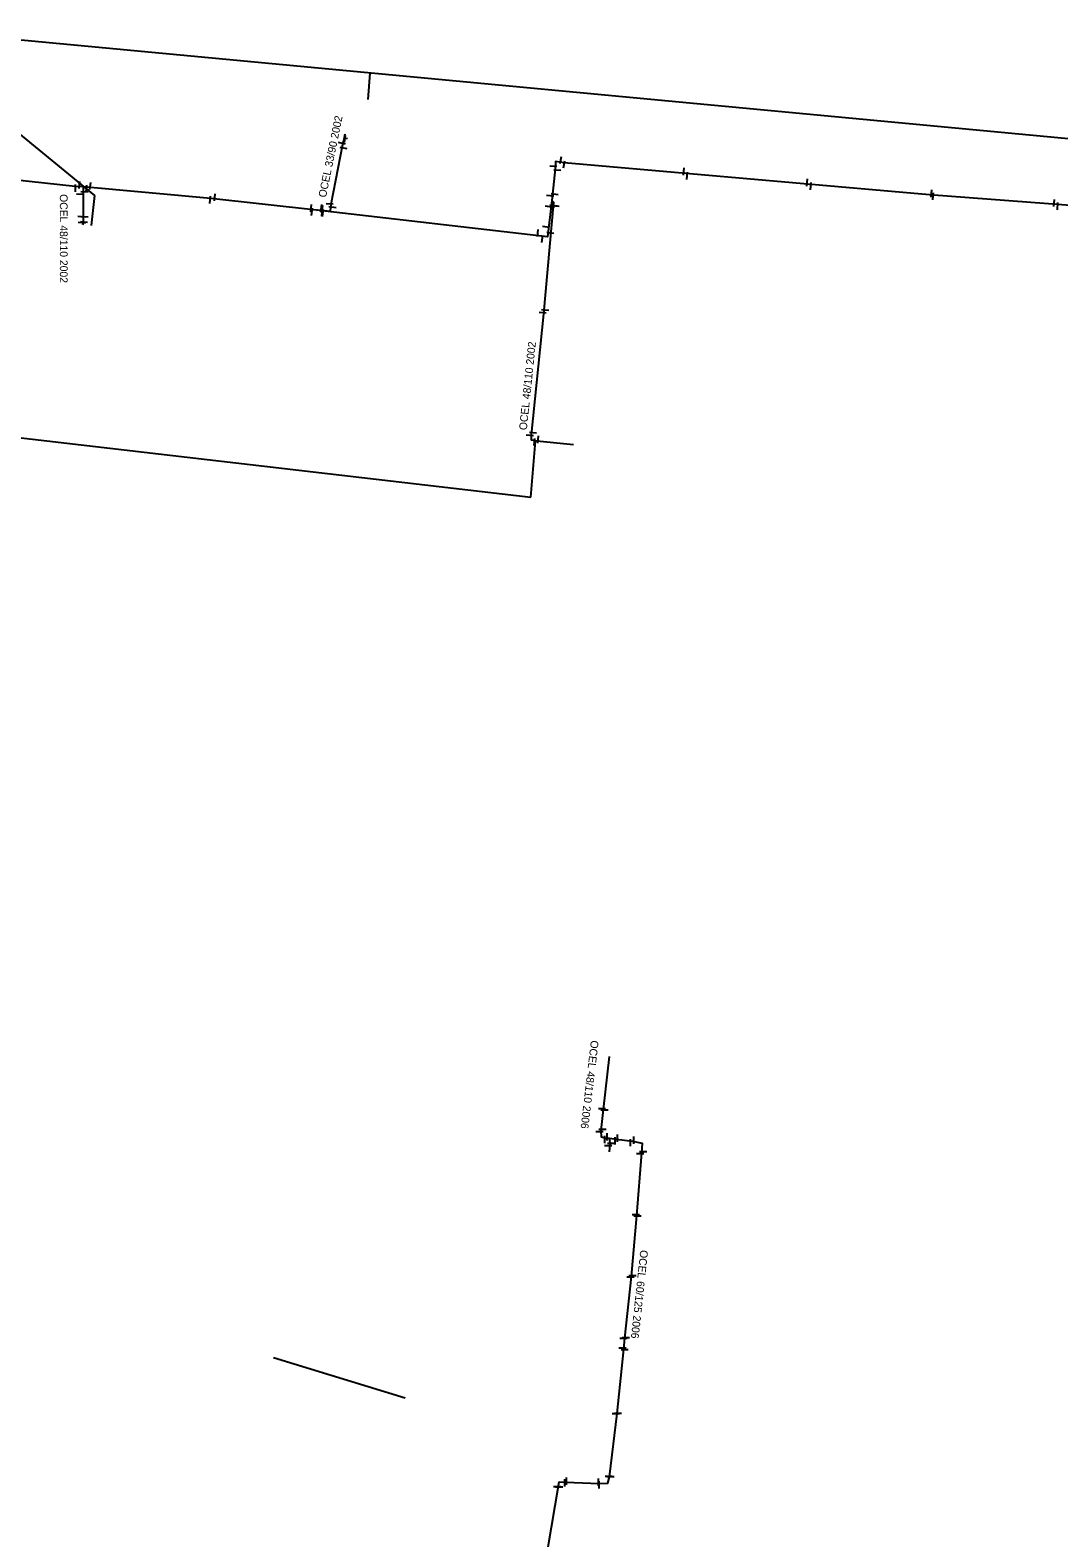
# Model space of a CAD drawing. Extents: x -642943 to -623314, y -1138561 to -1113539.
# Drawn here: x -642652 to -642552.6, y -1114240.7 to -1114094.9 of the extents above; entities that cross this region are included whole.
import ezdxf

# ---------------------------------------------------------------- set-up
doc = ezdxf.new("R2010")
doc.units = 0
for name, color, linetype in [('horkovod dimenze', 7, 'Continuous'), ('horkovod předisol', 7, 'Continuous'), ('horkovod sváry', 7, 'Continuous'), ('horkovod trasa', 7, 'Continuous'), ('horkovod zrušený', 7, 'Continuous')]:
    doc.layers.add(name, color=color, linetype=linetype)

# ---------------------------------------------------------------- blocks, each defined once
blk = doc.blocks.new('SPH')
at = {"layer": 'horkovod sváry'}
blk.add_line((0, -0.035), (0, 0.035), dxfattribs=at)

msp = doc.modelspace()

# ---------------------------------------------------------------- linework, layer by layer
at = {"layer": 'horkovod předisol'}
for points in [[(-642646.93, -1114110.09), (-642647.68, -1114110.06), (-642659.59, -1114108.78), (-642670.77, -1114107.73), (-642683.7, -1114106.45)], [(-642624.37, -1114112.36), (-642624.25, -1114112.32), (-642623.03, -1114112.45), (-642622.95, -1114111.77), (-642621.81, -1114105.98), (-642621.67, -1114105.41), (-642621.38, -1114105.39)], [(-642540.43, -1114112.75), (-642565.12, -1114110.86), (-642600.43, -1114107.77), (-642601.27, -1114107.64), (-642601.29, -1114108.35), (-642601.64, -1114111.42)], [(-642646.93, -1114110.09), (-642646.93, -1114113.56), (-642646.98, -1114113.75)], [(-642624.37, -1114112.36), (-642634.58, -1114111.22), (-642646.93, -1114110.09)], [(-642601.64, -1114111.42), (-642602.04, -1114114.92), (-642624.37, -1114112.36)], [(-642601.64, -1114111.42), (-642601.48, -1114111.57), (-642602.42, -1114122.38), (-642603.61, -1114134.06), (-642603.62, -1114134.54), (-642603.07, -1114134.64), (-642599.52, -1114134.99)], [(-642596.05, -1114202.09), (-642596.4, -1114202.06), (-642596.84, -1114201.95), (-642596.86, -1114201.31), (-642596.64, -1114199.27), (-642596.04, -1114194.14)], [(-642602.05, -1114241.92), (-642600.93, -1114235.27), (-642600.27, -1114235.29), (-642597.05, -1114235.43), (-642596.21, -1114235.39), (-642596.06, -1114234.78), (-642595.32, -1114228.66), (-642594.68, -1114222.43), (-642594.57, -1114221.38), (-642593.92, -1114215.42), (-642593.41, -1114209.53), (-642592.92, -1114203.45), (-642592.85, -1114202.55), (-642593.81, -1114202.35), (-642595.4, -1114202.17), (-642596.05, -1114202.09)], [(-642596.05, -1114202.09), (-642596.02, -1114202.69), (-642596.08, -1114203.35)]]:
    msp.add_lwpolyline(points, dxfattribs=at)
at = {"layer": 'horkovod trasa'}
for points in [[(-642646.93, -1114110.09), (-642647.68, -1114110.06), (-642659.59, -1114108.78), (-642670.77, -1114107.73), (-642683.7, -1114106.45)], [(-642624.37, -1114112.36), (-642624.25, -1114112.32), (-642623.03, -1114112.45), (-642622.95, -1114111.77), (-642621.81, -1114105.98), (-642621.67, -1114105.41), (-642621.38, -1114105.39)], [(-642540.43, -1114112.75), (-642565.12, -1114110.86), (-642600.43, -1114107.77), (-642601.27, -1114107.64), (-642601.29, -1114108.35), (-642601.64, -1114111.42)], [(-642646.93, -1114110.09), (-642646.93, -1114113.56), (-642646.98, -1114113.75)], [(-642624.37, -1114112.36), (-642634.58, -1114111.22), (-642646.93, -1114110.09)], [(-642601.64, -1114111.42), (-642602.04, -1114114.92), (-642624.37, -1114112.36)], [(-642601.64, -1114111.42), (-642601.48, -1114111.57), (-642602.42, -1114122.38), (-642603.61, -1114134.06), (-642603.62, -1114134.54), (-642603.07, -1114134.64), (-642599.52, -1114134.99)], [(-642596.05, -1114202.09), (-642596.4, -1114202.06), (-642596.84, -1114201.95), (-642596.86, -1114201.31), (-642596.64, -1114199.27), (-642596.04, -1114194.14)], [(-642602.05, -1114241.92), (-642600.93, -1114235.27), (-642600.27, -1114235.29), (-642597.05, -1114235.43), (-642596.21, -1114235.39), (-642596.06, -1114234.78), (-642595.32, -1114228.66), (-642594.68, -1114222.43), (-642594.57, -1114221.38), (-642593.92, -1114215.42), (-642593.41, -1114209.53), (-642592.92, -1114203.45), (-642592.85, -1114202.55), (-642593.81, -1114202.35), (-642595.4, -1114202.17), (-642596.05, -1114202.09)], [(-642596.05, -1114202.09), (-642596.02, -1114202.69), (-642596.08, -1114203.35)]]:
    msp.add_lwpolyline(points, dxfattribs=at)
at = {"layer": 'horkovod zrušený'}
for p, q in [((-642512.97, -1114109.11), (-642663.27, -1114094.95)), ((-642664.26, -1114095.84), (-642645.82, -1114110.94)), ((-642619.2, -1114099.1), (-642619.4, -1114101.64)), ((-642645.82, -1114110.94), (-642646.13, -1114113.84)), ((-642653.21, -1114134.33), (-642603.66, -1114140.09)), ((-642603.66, -1114140.09), (-642603.19, -1114134.66)), ((-642628.54, -1114223.23), (-642615.79, -1114227.15))]:
    msp.add_line(p, q, dxfattribs=at)

# ---------------------------------------------------------------- block references
at = {"layer": 'horkovod sváry'}
for p, xscale, yscale, rotation in [((-642621.67, -1114105.33), 9.999986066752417, 9.999986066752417, -9.934024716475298), ((-642621.62, -1114105.47), 9.999996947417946, 9.999996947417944, -7.485137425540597), ((-642621.9, -1114105.9), 9.999985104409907, 9.999985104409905, 76.7593884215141), ((-642621.75, -1114106.35), 10.00001783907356, 10.00001783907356, 79.05487721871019), ((-642601.48, -1114108.11), 9.999996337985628, 9.999996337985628, 86.68229603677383), ((-642600.79, -1114107.53), 9.999976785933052, 9.99997678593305, 170.3949051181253), ((-642600.47, -1114107.95), 9.999988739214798, 9.999988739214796, 170.69001234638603), ((-642647.27, -1114109.92), 9.999979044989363, 9.999979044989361, -3.3663509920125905), ((-642601.09, -1114108.5), 10.00001876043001, 10.000018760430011, 89.11871092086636), ((-642588.86, -1114108.62), 9.999982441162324, 9.999982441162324, -5.2023760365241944), ((-642588.54, -1114109.03), 9.999990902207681, 9.999990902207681, -4.763686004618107), ((-642576.94, -1114109.67), 9.999995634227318, 9.999995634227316, -5.287837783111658), ((-642647.22, -1114110.82), 9.999998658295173, 9.999998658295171, 86.52006090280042), ((-642646.8, -1114110.6), 10.000004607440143, 10.000004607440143, 86.60853431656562), ((-642646.62, -1114110.27), 9.999987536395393, 9.999987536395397, 174.28945995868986), ((-642646.26, -1114110.02), 10.000001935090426, 10.000001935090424, 172.0304847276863), ((-642634.65, -1114111.35), 9.999983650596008, 9.999983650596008, -6.887340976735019), ((-642634.19, -1114111.11), 10.000000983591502, 10.000000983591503, -6.423161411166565), ((-642601.79, -1114110.96), 10.000015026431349, 10.000015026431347, 83.91154612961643), ((-642601.35, -1114110.82), 9.999984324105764, 9.99998432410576, 83.15726897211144), ((-642576.59, -1114110.02), 10.000004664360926, 10.000004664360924, -4.5139324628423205), ((-642564.94, -1114110.74), 9.999992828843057, 9.999992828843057, -4.974421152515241), ((-642564.77, -1114111.01), 9.99997759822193, 9.999977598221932, -4.384688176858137), ((-642624.89, -1114112.15), 9.999979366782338, 9.999979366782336, -4.864633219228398), ((-642624.8, -1114112.51), 9.999992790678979, 9.999992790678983, -6.709727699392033), ((-642623.9, -1114112.15), 10.000003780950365, 10.000003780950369, -6.666739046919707), ((-642623.82, -1114112.59), 9.999997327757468, 9.999997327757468, -6.892437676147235), ((-642623.81, -1114112.26), 10.000011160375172, 10.000011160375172, -6.3324133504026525), ((-642623.74, -1114112.62), 10.0000166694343, 10.000016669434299, -7.02547256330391), ((-642623.1, -1114111.73), 9.999979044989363, 9.999979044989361, -93.36635099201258), ((-642622.83, -1114112.05), 10.000013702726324, 10.000013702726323, -97.01660359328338), ((-642601.92, -1114112.01), 9.999993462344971, 9.99999346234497, 83.5225958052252), ((-642601.72, -1114112.04), 10.000020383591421, 10.000020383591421, 83.81145753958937), ((-642601.47, -1114111.92), 9.999990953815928, 9.999990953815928, 82.85029621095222), ((-642601.27, -1114111.96), 9.999985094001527, 9.999985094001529, 83.54433995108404), ((-642553.08, -1114111.65), 10.000051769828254, 10.000051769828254, -4.9875146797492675), ((-642552.74, -1114111.96), 9.99997788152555, 9.999977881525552, -4.103504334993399), ((-642647.09, -1114112.99), 9.999998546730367, 9.999998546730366, 86.61815403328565), ((-642647.04, -1114113.58), 10.000019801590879, 10.000019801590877, 85.36455813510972), ((-642646.84, -1114113.52), 10.00000879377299, 10.000008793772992, 84.74619724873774), ((-642646.8, -1114113.01), 10.000019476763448, 10.000019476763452, 87.00963514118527), ((-642602.19, -1114113.95), 10.000021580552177, 10.000021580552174, -97.01041527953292), ((-642602.98, -1114114.56), 10.0000166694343, 10.000016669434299, -7.02547256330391), ((-642602.54, -1114115.13), 10.0000166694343, 10.000016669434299, -7.02547256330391), ((-642601.77, -1114114.52), 10.000036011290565, 10.000036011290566, -97.92072841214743), ((-642602.51, -1114122.26), 9.999999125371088, 9.99999912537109, 84.87960731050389), ((-642602.27, -1114121.97), 10.00002057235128, 10.000020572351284, -95.41805937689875), ((-642603.75, -1114134.12), 10.000012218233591, 10.00001221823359, 84.58810009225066), ((-642603.45, -1114133.86), 9.999981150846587, 9.999981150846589, 84.7188531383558), ((-642602.96, -1114134.52), 9.999984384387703, 9.999984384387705, -5.525021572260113), ((-642603.29, -1114134.76), 9.999984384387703, 9.999984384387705, -5.525021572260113), ((-642596.78, -1114199.2), 10, 10, 90), ((-642596.53, -1114199.33), 10, 10, 90), ((-642596.72, -1114201.19), 10, 10, 90), ((-642597.02, -1114201.43), 10, 10, 90), ((-642596.19, -1114202.77), 10, 10, 90), ((-642595.9, -1114202.56), 10, 10, 90), ((-642593.09, -1114203.55), 10, 10, 90), ((-642592.79, -1114203.36), 10, 10, 90), ((-642593.51, -1114209.46), 10, 10, 90), ((-642593.35, -1114209.57), 10, 10, 90), ((-642594.02, -1114215.48), 10, 10, 90), ((-642593.83, -1114215.35), 10, 10, 90), ((-642594.7, -1114221.42), 10, 10, 90), ((-642594.47, -1114221.33), 10, 10, 90), ((-642594.8, -1114222.35), 10, 10, 90), ((-642594.59, -1114222.49), 10, 10, 90), ((-642595.45, -1114228.7), 10, 10, 90), ((-642595.23, -1114228.66), 10, 10, 90), ((-642596.13, -1114234.76), 10, 10, 90), ((-642595.95, -1114234.77), 10, 10, 90), ((-642601.11, -1114235.75), 10, 10, 90), ((-642600.91, -1114235.78), 10, 10, 90)]:
    msp.add_blockref('SPH', p, dxfattribs=dict(at, xscale=xscale, yscale=yscale, rotation=rotation))
at = {"layer": 'horkovod sváry', "xscale": 10, "yscale": 10}
for p in [(-642647.65, -1114110.22), (-642596.51, -1114202.17), (-642596.28, -1114201.92), (-642595.51, -1114202.29), (-642595.28, -1114202.04), (-642594.02, -1114202.48), (-642593.69, -1114202.23), (-642600.21, -1114235.2), (-642600.36, -1114235.35), (-642597.1, -1114235.29), (-642597.04, -1114235.55)]:
    msp.add_blockref('SPH', p, dxfattribs=at)

# ---------------------------------------------------------------- texts
at = {"layer": 'horkovod dimenze'}
for s, rotation, p in [('OCEL 33/90 2002', 78.3691, (-642623.46, -1114111.17)), ('OCEL 48/110 2002', 270, (-642649.17, -1114110.8)), ('OCEL 48/110 2002', 84.0312, (-642604.05, -1114133.64)), ('OCEL 48/110 2006', 263.2588, (-642597.84, -1114192.56)), ('OCEL 60/125 2006', 263.8913, (-642593.07, -1114212.83))]:
    msp.add_text(s, height=0.75, rotation=rotation, dxfattribs=at).set_placement(p)

doc.saveas('drawing.dxf')
